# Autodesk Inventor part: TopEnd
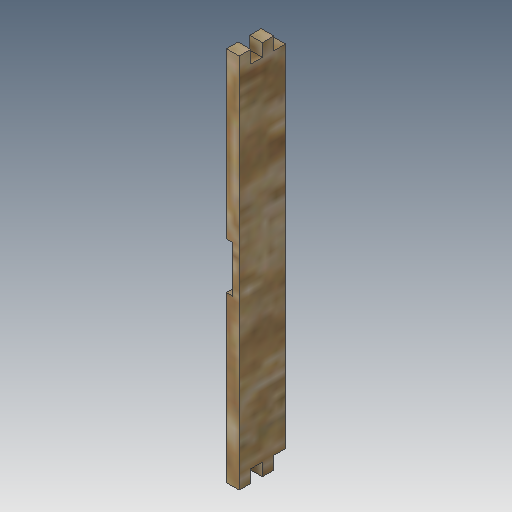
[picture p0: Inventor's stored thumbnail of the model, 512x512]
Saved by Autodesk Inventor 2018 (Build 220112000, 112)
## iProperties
Created: 2018-05
Part Number: TopEnd
Material: Generic
Document SubType Name: Modeling
Designer: arivu
Density: 1 g/cm^3
Appearance: Default
Author: arivu
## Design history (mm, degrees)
derived "WaterTank.ipt"
feature "Solid64::WaterTank.ipt" dims "d0" = 10
tag "TaggingFeature1"
body "Solid1"
